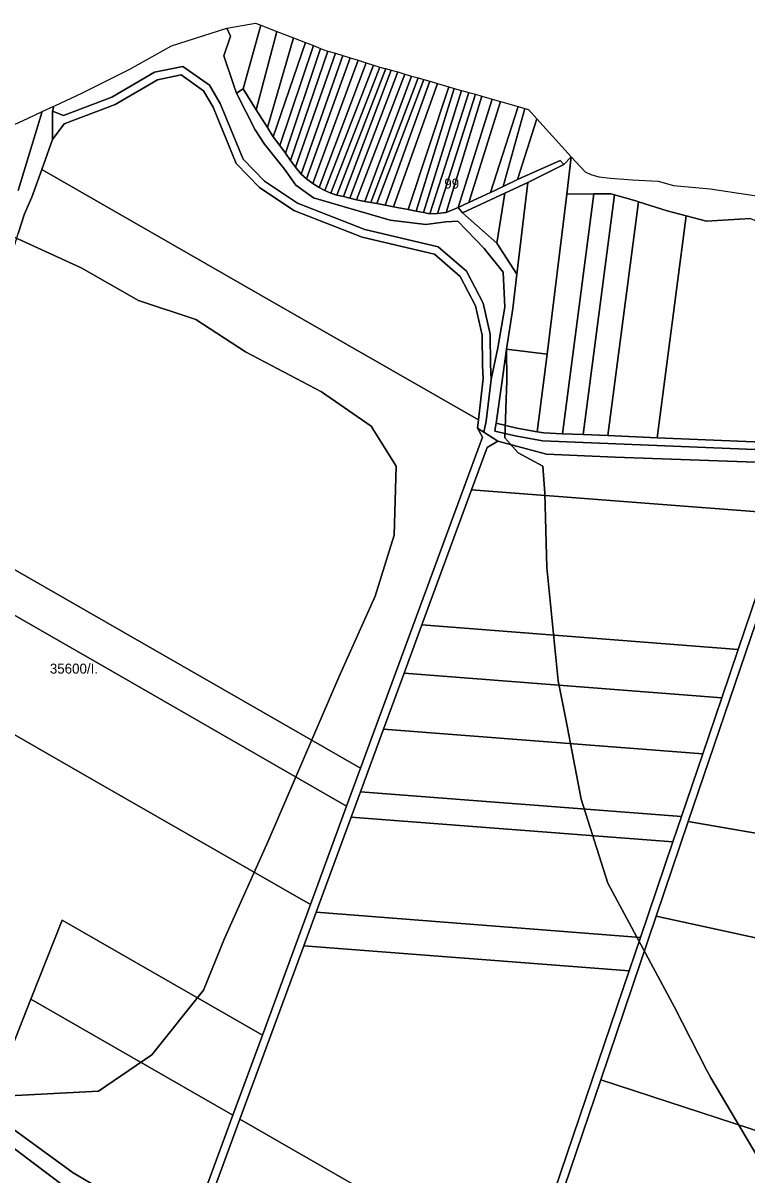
# Model space of a CAD drawing. Extents: x -545779 to -541342, y -1153413 to -1149956.
# Drawn here: x -542843 to -542480, y -1150533 to -1149956 of the extents above; entities that cross this region are included whole.
import ezdxf

# ---------------------------------------------------------------- set-up
doc = ezdxf.new("R2010")
doc.units = 0
for name, color, linetype in [('95560013', 7, 'Continuous'), ('95610013', 7, 'Continuous'), ('95620013', 7, 'Continuous'), ('95630013', 7, 'Continuous'), ('95640013', 7, 'Continuous'), ('95660013', 7, 'Continuous')]:
    doc.layers.add(name, color=color, linetype=linetype)

msp = doc.modelspace()

# ---------------------------------------------------------------- linework, layer by layer
at = {"layer": '95560013'}
for points in [[(-542623.67, -1150082.76), (-542615.89, -1150097.52), (-542612.63, -1150112.17), (-542612.48, -1150127.4), (-542612.12, -1150134.01), (-542614.51, -1150154.77), (-542724.03, -1150091.95), (-542833.56, -1150029.13), (-542828.22, -1150014.14), (-542822.34, -1150006.2), (-542796.71, -1149996.56), (-542775.53, -1149984.19), (-542763.66, -1149981.71), (-542752.49, -1149989.65), (-542747.63, -1149997.87), (-542735.94, -1150026.14), (-542724.33, -1150038.13), (-542707.15, -1150049.69), (-542672.73, -1150063.03), (-542636.6, -1150071.61)], [(-542510.29, -1150052.39), (-542500.06, -1150055.02), (-542477.95, -1150053.7), (-542463.98, -1150059.65), (-542457.08, -1150055.7), (-542451.95, -1150045.83), (-542450.09, -1150032.26), (-542445.04, -1150023.68), (-542436.5, -1150018.33), (-542455.87, -1150166.61), (-542524.83, -1150163.68)], [(-542782.39, -1150267.04), (-542891.21, -1150204.63), (-542881.9, -1150175.5), (-542869.26, -1150137.55), (-542857.09, -1150099.45), (-542845.4, -1150061.2), (-542842.25, -1150051.33), (-542838.52, -1150043.04), (-542833.56, -1150029.13), (-542724.03, -1150091.95), (-542614.51, -1150154.77), (-542614.98, -1150158.86), (-542612.5, -1150163.4), (-542673.59, -1150329.44)], [(-542572.32, -1150161.66), (-542581.69, -1150161.26), (-542585.02, -1150160.67), (-542579.93, -1150121.71), (-542570.18, -1150041.45), (-542556.62, -1150041.43)], [(-542572.32, -1150161.66), (-542556.62, -1150041.43), (-542547.98, -1150041.42), (-542546.19, -1150041.92), (-542561.89, -1150162.1)], [(-542561.89, -1150162.1), (-542546.19, -1150041.92), (-542535.58, -1150044.86), (-542534.23, -1150045.29), (-542549.56, -1150162.63)], [(-542534.23, -1150045.29), (-542519.82, -1150049.94), (-542510.29, -1150052.39), (-542524.83, -1150163.68), (-542549.56, -1150162.63)], [(-542605.64, -1150156.38), (-542602.75, -1150136.3), (-542600.39, -1150119.23), (-542579.93, -1150121.71), (-542585.02, -1150160.67), (-542595.21, -1150158.84)], [(-542545.94, -1150173.38), (-542456.55, -1150176.66), (-542453.84, -1150180.6), (-542461.06, -1150201.86), (-542617.93, -1150189.75), (-542610.13, -1150168.54), (-542604.8, -1150165.43), (-542580.39, -1150171.87)], [(-542484.16, -1150269.89), (-542642.91, -1150257.63), (-542617.93, -1150189.75), (-542461.06, -1150201.86)], [(-542897.56, -1150224), (-542891.21, -1150204.63), (-542782.39, -1150267.04), (-542673.59, -1150329.44), (-542680.59, -1150348.45), (-542789.08, -1150286.22)], [(-542789.08, -1150286.22), (-542680.59, -1150348.45), (-542698.75, -1150397.83), (-542806.43, -1150336.07), (-542914.11, -1150274.31), (-542897.56, -1150224)], [(-542642.91, -1150257.63), (-542484.16, -1150269.89), (-542492.37, -1150294.09), (-542651.79, -1150281.78)], [(-542336.2, -1150386.13), (-542509.19, -1150356.24), (-542475.36, -1150256.48), (-542342.22, -1150261.37), (-542339.31, -1150318.67)], [(-542885.74, -1150488.88), (-542939.27, -1150470.05), (-542957.08, -1150457.18), (-542973.67, -1150440.8), (-542978.05, -1150433.99), (-542977.98, -1150431.6), (-542977.86, -1150427.24), (-542975.75, -1150423.15), (-542960.11, -1150404.77), (-542954.03, -1150395.7), (-542949.96, -1150385.51), (-542948.44, -1150379.28), (-542944.25, -1150355.53), (-542933.12, -1150327.25), (-542928.95, -1150316.13), (-542914.11, -1150274.31), (-542806.43, -1150336.07), (-542698.75, -1150397.83), (-542722.86, -1150463.35), (-542823.35, -1150405.71), (-542839.07, -1150445.37), (-542861.66, -1150502.34)], [(-542492.37, -1150294.09), (-542501.94, -1150322.27), (-542662.14, -1150309.9), (-542651.79, -1150281.78)], [(-542678.36, -1150353.99), (-542673.7, -1150341.32), (-542512.63, -1150353.76), (-542516.94, -1150366.45)], [(-542695.93, -1150401.74), (-542678.36, -1150353.99), (-542516.94, -1150366.45), (-542533.19, -1150414.3)], [(-542332.68, -1150445.62), (-542525.28, -1150403.7), (-542509.19, -1150356.24), (-542336.2, -1150386.13)], [(-542702.1, -1150418.51), (-542695.93, -1150401.74), (-542533.19, -1150414.3), (-542538.9, -1150431.11)], [(-542330.19, -1150487.71), (-542329.65, -1150527.02), (-542335.84, -1150556.5), (-542444.5, -1150521.18), (-542553.15, -1150485.85), (-542525.28, -1150403.7), (-542332.68, -1150445.62)], [(-542722.86, -1150463.35), (-542737.65, -1150503.54), (-542839.07, -1150445.37), (-542823.35, -1150405.71)], [(-542645.66, -1150634.13), (-542678.6, -1150611.44), (-542693.55, -1150601.76), (-542672.83, -1150540.72), (-542734.13, -1150505.55), (-542702.1, -1150418.51), (-542538.9, -1150431.11), (-542576.35, -1150541.42), (-542613.8, -1150651.74), (-542618.41, -1150654.69), (-542628.79, -1150645.63)], [(-542763.51, -1150562.3), (-542783.62, -1150552.52), (-542817.82, -1150532.5), (-542849.86, -1150508.94), (-542861.66, -1150502.34), (-542839.07, -1150445.37), (-542737.65, -1150503.54), (-542758.53, -1150560.29)], [(-542337.68, -1150565.29), (-542355.74, -1150632.12), (-542463.52, -1150585.76), (-542571.31, -1150539.39), (-542553.15, -1150485.85), (-542444.5, -1150521.18), (-542335.84, -1150556.5)], [(-542747.63, -1150570.02), (-542752.7, -1150567.55), (-542754.92, -1150562.05), (-542734.13, -1150505.55), (-542672.83, -1150540.72), (-542693.55, -1150601.76), (-542712.51, -1150589.48)]]:
    msp.add_lwpolyline(points, close=True, dxfattribs=at)
at = {"layer": '95610013'}
msp.add_lwpolyline([(-542662.14, -1150309.9), (-542501.94, -1150322.27), (-542512.63, -1150353.76), (-542673.7, -1150341.32)], close=True, dxfattribs=at)
at = {"layer": '95620013'}
for points in [[(-542742.17, -1149972.19), (-542738.92, -1149962.27), (-542740.73, -1149958.23), (-542726.36, -1149955.69), (-542723.57, -1149956.76), (-542732.51, -1149988.72), (-542735.82, -1149990.88), (-542737.34, -1149986.56)], [(-542715.56, -1149959.94), (-542725.99, -1149999.16), (-542732.51, -1149988.72), (-542723.57, -1149956.76)], [(-542715.56, -1149959.94), (-542707.31, -1149963.03), (-542720.33, -1150008.13), (-542725.99, -1149999.16)], [(-542720.33, -1150008.13), (-542707.31, -1149963.03), (-542701.31, -1149965.4), (-542717.48, -1150012.81)], [(-542701.31, -1149965.4), (-542697.28, -1149966.93), (-542714.12, -1150017.05), (-542717.48, -1150012.81)], [(-542693.64, -1149968.41), (-542711.28, -1150020.96), (-542714.12, -1150017.05), (-542697.28, -1149966.93)], [(-542693.64, -1149968.41), (-542692.03, -1149969.06), (-542689.99, -1149969.76), (-542708.81, -1150024.58), (-542711.28, -1150020.96)], [(-542706.2, -1150027.96), (-542708.81, -1150024.58), (-542689.99, -1149969.76), (-542686.19, -1149970.84)], [(-542703.47, -1150031.54), (-542706.2, -1150027.96), (-542686.19, -1149970.84), (-542682.53, -1149971.95)], [(-542678.83, -1149973.15), (-542700.68, -1150033.88), (-542703.47, -1150031.54), (-542682.53, -1149971.95)], [(-542697.49, -1150036.19), (-542700.68, -1150033.88), (-542678.83, -1149973.15), (-542674.85, -1149974.34)], [(-542697.49, -1150036.19), (-542674.85, -1149974.34), (-542670.79, -1149975.65), (-542694.43, -1150038.11)], [(-542667.12, -1149976.75), (-542691.5, -1150039.73), (-542694.43, -1150038.11), (-542670.79, -1149975.65)], [(-542667.12, -1149976.75), (-542663.96, -1149977.75), (-542688.49, -1150040.99), (-542691.5, -1150039.73)], [(-542688.49, -1150040.99), (-542663.96, -1149977.75), (-542662.04, -1149978.25), (-542660.93, -1149978.57), (-542685.45, -1150041.96)], [(-542658.24, -1149979.32), (-542682.15, -1150042.76), (-542685.45, -1150041.96), (-542660.93, -1149978.57)], [(-542658.24, -1149979.32), (-542654.96, -1149980.15), (-542678.94, -1150043.58), (-542682.15, -1150042.76)], [(-542654.96, -1149980.15), (-542651.47, -1149981.27), (-542675.6, -1150044.42), (-542678.94, -1150043.58)], [(-542651.47, -1149981.27), (-542648.08, -1149982.3), (-542671.48, -1150045.14), (-542675.6, -1150044.42)], [(-542671.48, -1150045.14), (-542648.08, -1149982.3), (-542644.76, -1149983.2), (-542668.53, -1150045.63)], [(-542641.79, -1149984.09), (-542665.43, -1150046.28), (-542668.53, -1150045.63), (-542644.76, -1149983.2)], [(-542665.43, -1150046.28), (-542641.79, -1149984.09), (-542638.83, -1149984.89), (-542661.28, -1150047.08)], [(-542657.07, -1150047.85), (-542661.28, -1150047.08), (-542638.83, -1149984.89), (-542635.05, -1149986.05)], [(-542635.05, -1149986.05), (-542629.39, -1149987.63), (-542649.71, -1150049.27), (-542657.07, -1150047.85)], [(-542629.39, -1149987.63), (-542626.57, -1149988.45), (-542645.73, -1150050.02), (-542649.71, -1150049.27)], [(-542642.02, -1150050.8), (-542645.73, -1150050.02), (-542626.57, -1149988.45), (-542623.04, -1149989.49)], [(-542619.36, -1149990.47), (-542638.79, -1150051.44), (-542642.02, -1150050.8), (-542623.04, -1149989.49)], [(-542638.79, -1150051.44), (-542619.36, -1149990.47), (-542615.93, -1149991.44), (-542635.02, -1150051.17)], [(-542630.72, -1150050.77), (-542635.02, -1150051.17), (-542615.93, -1149991.44), (-542612.73, -1149992.41)], [(-542630.72, -1150050.77), (-542612.73, -1149992.41), (-542607.66, -1149993.89), (-542624.68, -1150048.26)], [(-542624.68, -1150048.26), (-542607.66, -1149993.89), (-542603.49, -1149995.02), (-542619.24, -1150045.68)], [(-542603.49, -1149995.02), (-542594.54, -1149997.6), (-542608.45, -1150040.68), (-542619.24, -1150045.68)], [(-542602.01, -1150037.74), (-542608.45, -1150040.68), (-542594.54, -1149997.6), (-542591.2, -1149998.56)], [(-542591.2, -1149998.56), (-542589.39, -1149999.09), (-542585.14, -1150003.72), (-542594.82, -1150034.12), (-542602.01, -1150037.74)], [(-542571.57, -1150026.72), (-542573.48, -1150024.63), (-542594.82, -1150034.12), (-542585.14, -1150003.72), (-542567.91, -1150022.74)], [(-542597.14, -1150098.85), (-542595.24, -1150081.58), (-542589.76, -1150035.73), (-542571.57, -1150026.72), (-542567.91, -1150022.74), (-542570.18, -1150041.45), (-542579.93, -1150121.71), (-542600.39, -1150119.23)], [(-542605.33, -1150066.14), (-542601.29, -1150041.03), (-542589.76, -1150035.73), (-542595.24, -1150081.58)], [(-542605.33, -1150066.14), (-542622.44, -1150050.92), (-542601.29, -1150041.03)]]:
    msp.add_lwpolyline(points, close=True, dxfattribs=at)
at = {"layer": '95630013'}
msp.add_lwpolyline([(-542456.55, -1150176.66), (-542545.94, -1150173.38), (-542580.39, -1150171.87), (-542604.8, -1150165.43), (-542611.81, -1150160.9), (-542610.56, -1150155.41), (-542608.15, -1150134.47), (-542604.81, -1150118.6), (-542601.21, -1150098.14), (-542602.07, -1150080.64), (-542611.67, -1150068.73), (-542624.74, -1150055.09), (-542630.88, -1150055.38), (-542640.86, -1150056.79), (-542658.73, -1150054.62), (-542674.35, -1150049.99), (-542697.29, -1150043.36), (-542706.1, -1150037.09), (-542711.7, -1150028.91), (-542721.87, -1150016.53), (-542726.5, -1150009.29), (-542735.82, -1149990.88), (-542732.51, -1149988.72), (-542725.99, -1149999.16), (-542720.33, -1150008.13), (-542717.48, -1150012.81), (-542714.12, -1150017.05), (-542711.28, -1150020.96), (-542708.81, -1150024.58), (-542706.2, -1150027.96), (-542703.47, -1150031.54), (-542700.68, -1150033.88), (-542697.49, -1150036.19), (-542694.43, -1150038.11), (-542691.5, -1150039.73), (-542688.49, -1150040.99), (-542685.45, -1150041.96), (-542682.15, -1150042.76), (-542678.94, -1150043.58), (-542675.6, -1150044.42), (-542671.48, -1150045.14), (-542668.53, -1150045.63), (-542665.43, -1150046.28), (-542661.28, -1150047.08), (-542657.07, -1150047.85), (-542649.71, -1150049.27), (-542645.73, -1150050.02), (-542642.02, -1150050.8), (-542638.79, -1150051.44), (-542635.02, -1150051.17), (-542630.72, -1150050.77), (-542624.68, -1150048.26), (-542619.24, -1150045.68), (-542608.45, -1150040.68), (-542602.01, -1150037.74), (-542594.82, -1150034.12), (-542573.48, -1150024.63), (-542571.57, -1150026.72), (-542589.76, -1150035.73), (-542601.29, -1150041.03), (-542622.44, -1150050.92), (-542605.33, -1150066.14), (-542595.24, -1150081.58), (-542597.14, -1150098.85), (-542600.39, -1150119.23), (-542602.75, -1150136.3), (-542605.64, -1150156.38), (-542606.18, -1150160.11), (-542606.21, -1150160.36), (-542596.02, -1150162.76), (-542582.4, -1150165.2), (-542463.56, -1150170.13)], dxfattribs=at)
at = {"layer": '95640013'}
for points in [[(-542735.82, -1149990.88), (-542726.5, -1150009.29), (-542721.87, -1150016.53), (-542711.7, -1150028.91), (-542706.1, -1150037.09), (-542697.29, -1150043.36), (-542674.35, -1150049.99), (-542658.73, -1150054.62), (-542640.86, -1150056.79), (-542630.88, -1150055.38), (-542624.74, -1150055.09), (-542611.67, -1150068.73), (-542602.07, -1150080.64), (-542601.21, -1150098.14), (-542604.81, -1150118.6), (-542608.15, -1150134.47), (-542608.49, -1150126.77), (-542608.63, -1150111.71), (-542612.1, -1150096.13), (-542620.48, -1150080.22), (-542634.73, -1150067.94), (-542671.54, -1150059.2), (-542705.29, -1150046.12), (-542721.75, -1150035.05), (-542732.53, -1150023.91), (-542744.04, -1149996.08), (-542749.48, -1149986.88), (-542762.77, -1149977.44), (-542776.92, -1149980.39), (-542798.44, -1149992.94), (-542822.69, -1150002.06), (-542828.09, -1149999.82), (-542827.44, -1149997.4), (-542826.65, -1149997.04), (-542813.4, -1149990.93), (-542789.38, -1149978.91), (-542768.46, -1149967.13), (-542740.73, -1149958.23), (-542738.92, -1149962.27), (-542742.17, -1149972.19), (-542737.34, -1149986.56)], [(-542612.63, -1150112.17), (-542615.89, -1150097.52), (-542623.67, -1150082.76), (-542636.6, -1150071.61), (-542672.73, -1150063.03), (-542707.15, -1150049.69), (-542724.33, -1150038.13), (-542735.94, -1150026.14), (-542747.63, -1149997.87), (-542752.49, -1149989.65), (-542763.66, -1149981.71), (-542775.53, -1149984.19), (-542796.71, -1149996.56), (-542822.34, -1150006.2), (-542828.22, -1150014.14), (-542828.09, -1149999.82), (-542822.69, -1150002.06), (-542798.44, -1149992.94), (-542776.92, -1149980.39), (-542762.77, -1149977.44), (-542749.48, -1149986.88), (-542744.04, -1149996.08), (-542732.53, -1150023.91), (-542721.75, -1150035.05), (-542705.29, -1150046.12), (-542671.54, -1150059.2), (-542634.73, -1150067.94), (-542620.48, -1150080.22), (-542612.1, -1150096.13), (-542608.63, -1150111.71), (-542608.49, -1150126.77), (-542608.15, -1150134.47), (-542610.56, -1150155.41), (-542611.81, -1150160.9), (-542614.98, -1150158.86), (-542614.51, -1150154.77), (-542612.12, -1150134.01), (-542612.48, -1150127.4)], [(-542596.02, -1150162.76), (-542606.21, -1150160.36), (-542606.18, -1150160.11), (-542605.64, -1150156.38), (-542595.21, -1150158.84), (-542585.02, -1150160.67), (-542581.69, -1150161.26), (-542572.32, -1150161.66), (-542561.89, -1150162.1), (-542549.56, -1150162.63), (-542524.83, -1150163.68), (-542455.87, -1150166.61), (-542350.02, -1150171.11), (-542346.88, -1150166.67), (-542346.14, -1150164.21), (-542342.14, -1150164.82), (-542343.24, -1150168.45), (-542347.94, -1150175.1), (-542364.21, -1150174.51), (-542463.56, -1150170.13), (-542582.4, -1150165.2)], [(-542680.59, -1150348.45), (-542673.59, -1150329.44), (-542612.5, -1150163.4), (-542614.98, -1150158.86), (-542611.81, -1150160.9), (-542604.8, -1150165.43), (-542610.13, -1150168.54), (-542617.93, -1150189.75), (-542642.91, -1150257.63), (-542651.79, -1150281.78), (-542662.14, -1150309.9), (-542673.7, -1150341.32), (-542678.36, -1150353.99), (-542695.93, -1150401.74), (-542702.1, -1150418.51), (-542734.13, -1150505.55), (-542754.92, -1150562.05), (-542752.7, -1150567.55), (-542763.51, -1150562.3), (-542758.53, -1150560.29), (-542737.65, -1150503.54), (-542722.86, -1150463.35), (-542698.75, -1150397.83)]]:
    msp.add_lwpolyline(points, close=True, dxfattribs=at)
for points in [[(-542870, -1150017), (-542840.72, -1150003.52), (-542833.36, -1150000.13), (-542845.33, -1150039.61)], [(-542845.33, -1150039.61), (-542833.36, -1150000.13), (-542827.44, -1149997.4), (-542828.09, -1149999.82), (-542828.22, -1150014.14), (-542833.56, -1150029.13), (-542838.52, -1150043.04), (-542842.25, -1150051.33), (-542845.4, -1150061.2)], [(-542477.95, -1150053.7), (-542500.06, -1150055.02), (-542510.29, -1150052.39), (-542519.82, -1150049.94), (-542534.23, -1150045.29), (-542535.58, -1150044.86), (-542546.19, -1150041.92), (-542547.98, -1150041.42), (-542556.62, -1150041.43), (-542570.18, -1150041.45), (-542567.91, -1150022.74), (-542560.89, -1150030.36), (-542558.09, -1150031.74), (-542554.09, -1150032.87), (-542548.28, -1150033.49), (-542537.17, -1150034.26), (-542524.38, -1150035.08), (-542516.56, -1150037.16), (-542498.22, -1150038.93), (-542466.12, -1150043.78)], [(-542576.35, -1150541.42), (-542538.9, -1150431.11), (-542533.19, -1150414.3), (-542516.94, -1150366.45), (-542512.63, -1150353.76), (-542501.94, -1150322.27), (-542492.37, -1150294.09), (-542484.16, -1150269.89), (-542461.06, -1150201.86), (-542453.84, -1150180.6), (-542456.55, -1150176.66), (-542444.39, -1150177.12), (-542449.67, -1150180.76), (-542455.33, -1150197.45), (-542463.83, -1150222.51), (-542475.36, -1150256.48), (-542509.19, -1150356.24), (-542525.28, -1150403.7), (-542553.15, -1150485.85), (-542571.31, -1150539.39)], [(-542849.86, -1150508.94), (-542817.82, -1150532.5), (-542783.62, -1150552.52)], [(-542854.19, -1150515.06), (-542822.11, -1150539.26)], [(-542822.11, -1150539.26), (-542854.19, -1150515.06)]]:
    msp.add_lwpolyline(points, dxfattribs=at)
at = {"layer": '95660013'}
for points in [[(-542845.33, -1150039.61), (-542833.36, -1150000.13), (-542827.44, -1149997.4), (-542826.65, -1149997.04), (-542813.4, -1149990.93), (-542789.38, -1149978.91), (-542768.46, -1149967.13), (-542740.73, -1149958.23), (-542738.92, -1149962.27), (-542742.17, -1149972.19), (-542737.34, -1149986.56), (-542735.82, -1149990.88), (-542732.51, -1149988.72), (-542725.99, -1149999.16), (-542720.33, -1150008.13), (-542717.48, -1150012.81), (-542714.12, -1150017.05), (-542711.28, -1150020.96), (-542708.81, -1150024.58), (-542706.2, -1150027.96), (-542703.47, -1150031.54), (-542700.68, -1150033.88), (-542697.49, -1150036.19), (-542694.43, -1150038.11), (-542691.5, -1150039.73), (-542688.49, -1150040.99), (-542685.45, -1150041.96), (-542682.15, -1150042.76), (-542678.94, -1150043.58), (-542675.6, -1150044.42), (-542671.48, -1150045.14), (-542668.53, -1150045.63), (-542665.43, -1150046.28), (-542661.28, -1150047.08), (-542657.07, -1150047.85), (-542649.71, -1150049.27), (-542645.73, -1150050.02), (-542642.02, -1150050.8), (-542638.79, -1150051.44), (-542635.02, -1150051.17), (-542630.72, -1150050.77), (-542624.68, -1150048.26), (-542622.44, -1150050.92), (-542605.33, -1150066.14), (-542595.24, -1150081.58), (-542597.14, -1150098.85), (-542600.39, -1150119.23), (-542600.314, -1150134.976), (-542601.27, -1150163.685), (-542594.572, -1150171.341), (-542582.131, -1150178.04), (-542581.173, -1150191.438), (-542580.217, -1150228.76), (-542574.474, -1150285.7), (-542570.647, -1150304.839), (-542562.991, -1150345.032), (-542549.594, -1150387.139), (-542516.099, -1150449.342), (-542500, -1150480.696), (-542497.917, -1150484.75), (-542467.294, -1150536.427)], [(-542870, -1150017), (-542840.72, -1150003.52), (-542833.36, -1150000.13), (-542845.33, -1150039.61)], [(-542467.294, -1150536.427), (-542497.917, -1150484.75), (-542500, -1150480.696), (-542516.099, -1150449.342), (-542549.594, -1150387.139), (-542562.991, -1150345.032), (-542570.647, -1150304.839), (-542574.474, -1150285.7), (-542580.217, -1150228.76), (-542581.173, -1150191.438), (-542582.131, -1150178.04), (-542594.572, -1150171.341), (-542601.27, -1150163.685), (-542600.314, -1150134.976), (-542600.39, -1150119.23), (-542579.93, -1150121.71), (-542570.18, -1150041.45), (-542567.91, -1150022.74), (-542560.89, -1150030.36), (-542558.09, -1150031.74), (-542554.09, -1150032.87), (-542548.28, -1150033.49), (-542537.17, -1150034.26), (-542524.38, -1150035.08), (-542516.56, -1150037.16), (-542498.22, -1150038.93), (-542466.12, -1150043.78)], [(-542851.744, -1150061.044), (-542813.719, -1150078.515), (-542785.009, -1150094.783), (-542756.3, -1150104.353), (-542731.419, -1150120.622), (-542693.14, -1150140.718), (-542668.259, -1150157.944), (-542655.818, -1150178.04), (-542656.774, -1150212.491), (-542666.344, -1150243.114), (-542684.528, -1150283.786), (-542719.936, -1150366.086), (-542741.945, -1150414.891), (-542752.471, -1150440.729), (-542778.311, -1150473.267), (-542805.105, -1150491.449), (-542859.653, -1150494.32)], [(-542859.653, -1150494.32), (-542805.105, -1150491.449), (-542778.311, -1150473.267), (-542752.471, -1150440.729), (-542741.945, -1150414.891), (-542719.936, -1150366.086), (-542684.528, -1150283.786), (-542666.344, -1150243.114), (-542656.774, -1150212.491), (-542655.818, -1150178.04), (-542668.259, -1150157.944), (-542693.14, -1150140.718), (-542731.419, -1150120.622), (-542756.3, -1150104.353), (-542785.009, -1150094.783), (-542813.719, -1150078.515), (-542851.744, -1150061.044)]]:
    msp.add_lwpolyline(points, dxfattribs=at)
msp.add_lwpolyline([(-542738.92, -1149962.27), (-542740.73, -1149958.23), (-542726.36, -1149955.69), (-542723.57, -1149956.76), (-542715.56, -1149959.94), (-542707.31, -1149963.03), (-542701.31, -1149965.4), (-542697.28, -1149966.93), (-542693.64, -1149968.41), (-542692.03, -1149969.06), (-542689.99, -1149969.76), (-542686.19, -1149970.84), (-542682.53, -1149971.95), (-542678.83, -1149973.15), (-542674.85, -1149974.34), (-542670.79, -1149975.65), (-542667.12, -1149976.75), (-542663.96, -1149977.75), (-542662.04, -1149978.25), (-542660.93, -1149978.57), (-542658.24, -1149979.32), (-542654.96, -1149980.15), (-542651.47, -1149981.27), (-542648.08, -1149982.3), (-542644.76, -1149983.2), (-542641.79, -1149984.09), (-542638.83, -1149984.89), (-542635.05, -1149986.05), (-542629.39, -1149987.63), (-542626.57, -1149988.45), (-542623.04, -1149989.49), (-542619.36, -1149990.47), (-542615.93, -1149991.44), (-542612.73, -1149992.41), (-542607.66, -1149993.89), (-542603.49, -1149995.02), (-542594.54, -1149997.6), (-542591.2, -1149998.56), (-542589.39, -1149999.09), (-542585.14, -1150003.72), (-542567.91, -1150022.74), (-542570.18, -1150041.45), (-542579.93, -1150121.71), (-542600.39, -1150119.23), (-542597.14, -1150098.85), (-542595.24, -1150081.58), (-542605.33, -1150066.14), (-542622.44, -1150050.92), (-542624.68, -1150048.26), (-542630.72, -1150050.77), (-542635.02, -1150051.17), (-542638.79, -1150051.44), (-542642.02, -1150050.8), (-542645.73, -1150050.02), (-542649.71, -1150049.27), (-542657.07, -1150047.85), (-542661.28, -1150047.08), (-542665.43, -1150046.28), (-542668.53, -1150045.63), (-542671.48, -1150045.14), (-542675.6, -1150044.42), (-542678.94, -1150043.58), (-542682.15, -1150042.76), (-542685.45, -1150041.96), (-542688.49, -1150040.99), (-542691.5, -1150039.73), (-542694.43, -1150038.11), (-542697.49, -1150036.19), (-542700.68, -1150033.88), (-542703.47, -1150031.54), (-542706.2, -1150027.96), (-542708.81, -1150024.58), (-542711.28, -1150020.96), (-542714.12, -1150017.05), (-542717.48, -1150012.81), (-542720.33, -1150008.13), (-542725.99, -1149999.16), (-542732.51, -1149988.72), (-542735.82, -1149990.88), (-542737.34, -1149986.56), (-542742.17, -1149972.19)], close=True, dxfattribs=at)

# ---------------------------------------------------------------- texts
for s, p in [('99', (-542631.605, -1150038.7)), ('35600/I.', (-542829.494, -1150282))]:
    msp.add_text(s, height=5, rotation=0, dxfattribs=at).set_placement(p)

doc.saveas('drawing.dxf')
